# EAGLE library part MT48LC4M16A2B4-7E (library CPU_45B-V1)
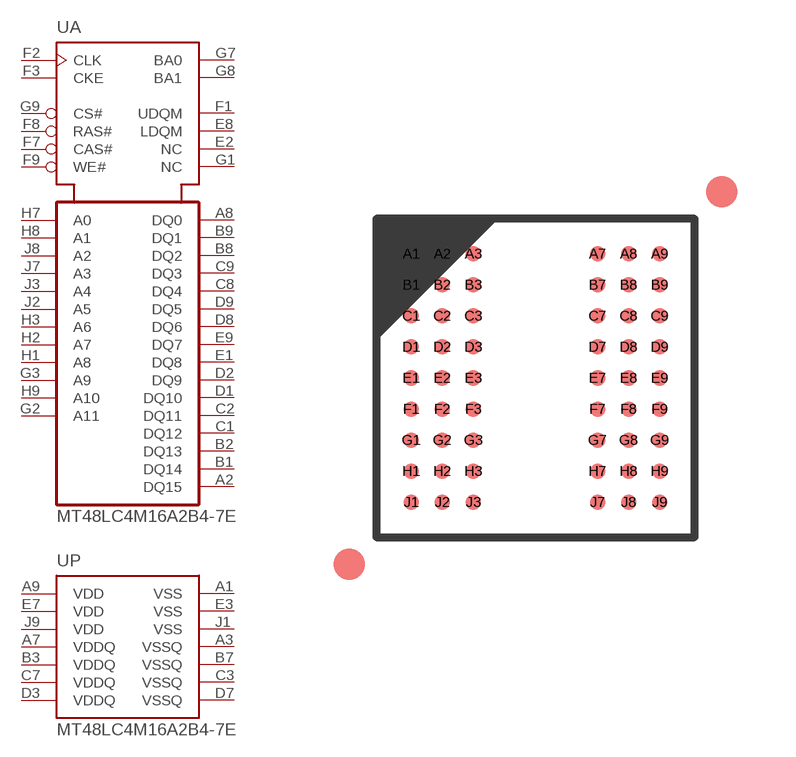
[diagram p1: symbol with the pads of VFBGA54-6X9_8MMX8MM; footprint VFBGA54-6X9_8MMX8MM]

Designator prefix U; gates A=X16_SDRAM_SYS_A0-A11 P=X16_SDRAM_PWR

## MT48LC4M16A2B4-7E  [VFBGA54-6X9_8MMX8MM]
A1  P:VSS  pwr
A2  A:DQ15
A3  P:VSSQ  pwr
A7  P:VDDQ  pwr
A8  A:DQ0
A9  P:VDD  pwr
B1  A:DQ14
B2  A:DQ13
B3  P:VDDQ  pwr
B7  P:VSSQ  pwr
B8  A:DQ2
B9  A:DQ1
C1  A:DQ12
C2  A:DQ11
C3  P:VSSQ  pwr
C7  P:VDDQ  pwr
C8  A:DQ4
C9  A:DQ3
D1  A:DQ10
D2  A:DQ9
D3  P:VDDQ  pwr
D7  P:VSSQ  pwr
D8  A:DQ6
D9  A:DQ5
E1  A:DQ8
E2  A:NC  nc
E3  P:VSS  pwr
E7  P:VDD  pwr
E8  A:LDQM  in
E9  A:DQ7
F1  A:UDQM  in
F2  A:CLK  in
F3  A:CKE  in
F7  A:CAS#  in
F8  A:RAS#  in
F9  A:WE#  in
G1  A:NC  nc
G2  A:A11  in
G3  A:A9  in
G7  A:BA0  in
G8  A:BA1  in
G9  A:CS#  in
H1  A:A8  in
H2  A:A7  in
H3  A:A6  in
H7  A:A0  in
H8  A:A1  in
H9  A:A10  in
J1  P:VSS  pwr
J2  A:A5  in
J3  A:A4  in
J7  A:A3  in
J8  A:A2  in
J9  P:VDD  pwr

## Footprint VFBGA54-6X9_8MMX8MM (pad centres in mm)
smd 0.4 x 0.4: A1 -3.2,3.2; A2 -2.4,3.2; A3 -1.6,3.2; A7 1.6,3.2; A8 2.4,3.2; A9 3.2,3.2; B1 -3.2,2.4; B2 -2.4,2.4; B3 -1.6,2.4; B7 1.6,2.4; B8 2.4,2.4; B9 3.2,2.4; C1 -3.2,1.6; C2 -2.4,1.6; C3 -1.6,1.6; C7 1.6,1.6; C8 2.4,1.6; C9 3.2,1.6; D1 -3.2,0.8; D2 -2.4,0.8; D3 -1.6,0.8; D7 1.6,0.8; D8 2.4,0.8; D9 3.2,0.8; E1 -3.2,0; E2 -2.4,0; E3 -1.6,0; E7 1.6,0; E8 2.4,0; E9 3.2,0; F1 -3.2,-0.8; F2 -2.4,-0.8; F3 -1.6,-0.8; F7 1.6,-0.8; F8 2.4,-0.8; F9 3.2,-0.8; G1 -3.2,-1.6; G2 -2.4,-1.6; G3 -1.6,-1.6; G7 1.6,-1.6; G8 2.4,-1.6; G9 3.2,-1.6; H1 -3.2,-2.4; H2 -2.4,-2.4; H3 -1.6,-2.4; H7 1.6,-2.4; H8 2.4,-2.4; H9 3.2,-2.4; J1 -3.2,-3.2; J2 -2.4,-3.2; J3 -1.6,-3.2; J7 1.6,-3.2; J8 2.4,-3.2; J9 3.2,-3.2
